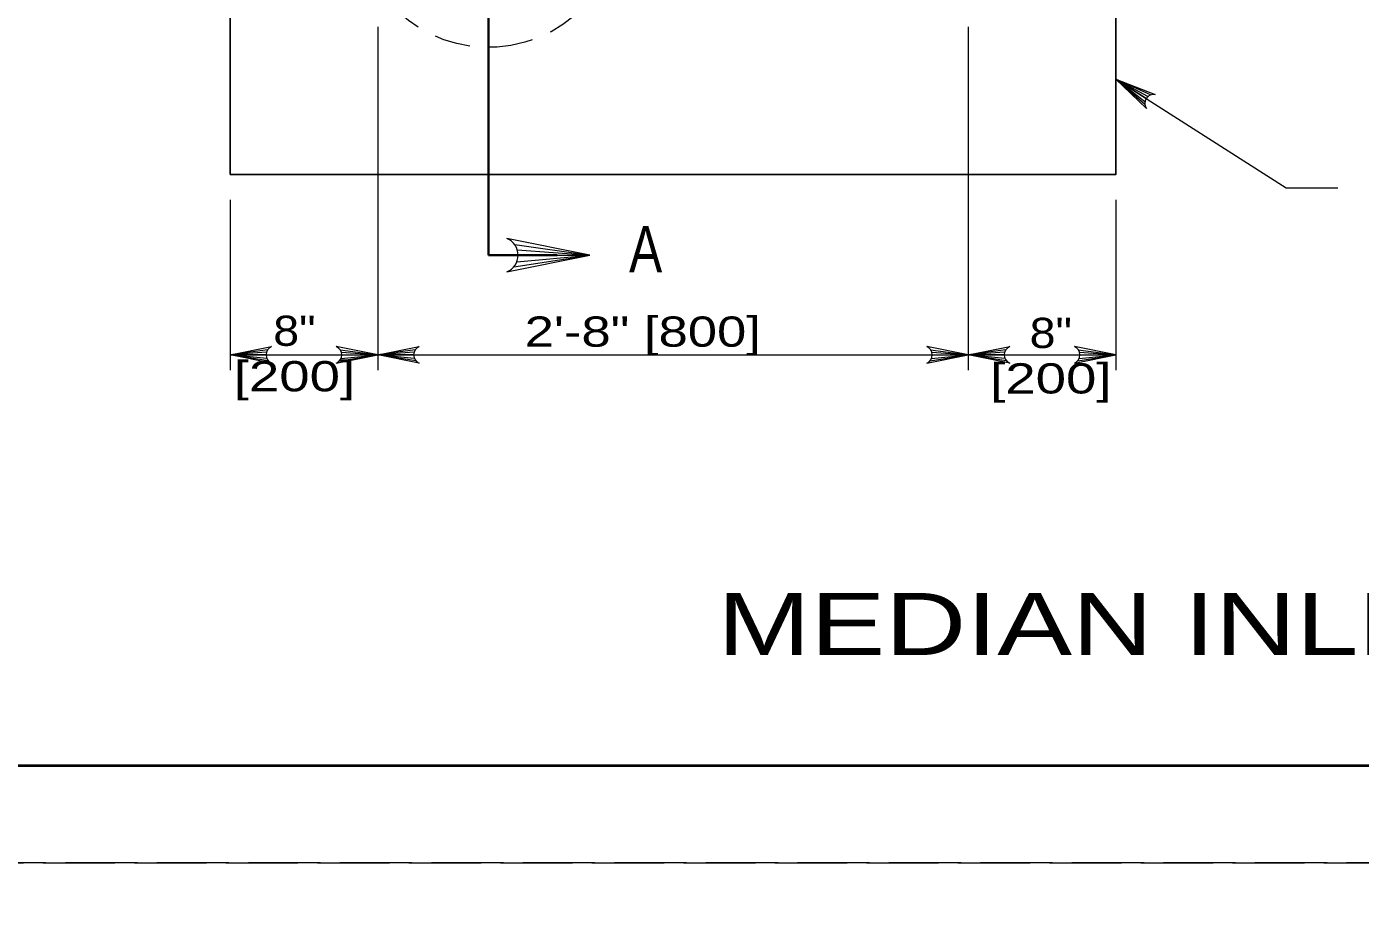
# Model space of a CAD drawing. Extents: x 339.1 to 373.1, y 1412.7 to 1456.7.
# Drawn here: x 344.17 to 351.05, y 1434.5 to 1439.06 of the extents above; entities that cross this region are included whole.
import ezdxf
from ezdxf.enums import TextEntityAlignment as Align

# ---------------------------------------------------------------- set-up
doc = ezdxf.new("R2010")
doc.units = 0
doc.header["$LTSCALE"] = 0.062
doc.linetypes.add('LONG_DASHED', pattern=[7.5, 6, -1.5])
doc.linetypes.add('MEDIUM_DASHED', pattern=[4.5, 3, -1.5])
doc.layers.add('1', color=7, linetype='Continuous', lineweight=13)

msp = doc.modelspace()

# ---------------------------------------------------------------- linework, layer by layer
at = {"layer": '1', "lineweight": 25}
msp.add_line((345.21833, 1441.19975), (345.21833, 1438.29742), dxfattribs=at)
at = {"layer": '1', "lineweight": 35}
for p, q in [((346.551, 1439.64317), (346.551, 1437.88075)), ((346.551, 1437.88075), (346.90592, 1437.88075))]:
    msp.add_line(p, q, dxfattribs=at)
at = {"layer": '1'}
for p, q in [((345.97983, 1439.05808), (345.97983, 1437.28725)), ((349.02583, 1439.05808), (349.02583, 1437.28725)), ((349.94333, 1438.689), (349.78733, 1438.789)), ((349.93683, 1438.6725), (349.78733, 1438.789)), ((349.93633, 1438.65792), (349.78733, 1438.789)), ((349.95242, 1438.6995), (349.78733, 1438.789)), ((349.96517, 1438.70725), (349.78733, 1438.789)), ((345.21833, 1438.16708), (345.21833, 1437.28725)), ((349.78733, 1438.16708), (349.78733, 1437.28725)), ((346.68667, 1437.935), (347.0745, 1437.88075)), ((346.68217, 1437.82083), (347.0745, 1437.88075)), ((346.697, 1437.84592), (347.0745, 1437.88075)), ((346.69983, 1437.90817), (347.0745, 1437.88075)), ((346.70383, 1437.88075), (347.0745, 1437.88075)), ((345.41225, 1437.39308), (345.21833, 1437.36592)), ((345.40567, 1437.37967), (345.21833, 1437.36592)), ((345.40367, 1437.36592), (345.21833, 1437.36592)), ((345.40708, 1437.3485), (345.21833, 1437.36592)), ((345.4145, 1437.33592), (345.21833, 1437.36592)), ((345.78367, 1437.33592), (345.97983, 1437.36592)), ((345.78592, 1437.39308), (345.97983, 1437.36592)), ((345.79108, 1437.3485), (345.97983, 1437.36592)), ((345.7925, 1437.37967), (345.97983, 1437.36592)), ((345.7945, 1437.36592), (345.97983, 1437.36592)), ((346.17375, 1437.39308), (345.97983, 1437.36592)), ((346.16717, 1437.37967), (345.97983, 1437.36592)), ((346.16517, 1437.36592), (345.97983, 1437.36592)), ((346.16858, 1437.3485), (345.97983, 1437.36592)), ((346.176, 1437.33592), (345.97983, 1437.36592)), ((348.82967, 1437.33592), (349.02583, 1437.36592)), ((348.83192, 1437.39308), (349.02583, 1437.36592)), ((348.83708, 1437.3485), (349.02583, 1437.36592)), ((348.8385, 1437.37967), (349.02583, 1437.36592)), ((348.8405, 1437.36592), (349.02583, 1437.36592)), ((349.21975, 1437.39308), (349.02583, 1437.36592)), ((349.21317, 1437.37967), (349.02583, 1437.36592)), ((349.21117, 1437.36592), (349.02583, 1437.36592)), ((349.21458, 1437.3485), (349.02583, 1437.36592)), ((349.222, 1437.33592), (349.02583, 1437.36592)), ((349.59117, 1437.33592), (349.78733, 1437.36592)), ((349.59342, 1437.39308), (349.78733, 1437.36592)), ((349.59858, 1437.3485), (349.78733, 1437.36592)), ((349.6, 1437.37967), (349.78733, 1437.36592)), ((349.602, 1437.36592), (349.78733, 1437.36592))]:
    msp.add_line(p, q, dxfattribs=at)
at = {"layer": '1', "linetype": 'LONG_DASHED'}
for points in [[(339.0605, 1434.7455), (373.0605, 1434.7455), (373.0605, 1456.7455), (339.0605, 1456.7455)], [(339.0605, 1412.7455), (373.0605, 1412.7455), (373.0605, 1434.7455), (339.0605, 1434.7455)]]:
    msp.add_lwpolyline(points, close=True, dxfattribs=at)
at = {"layer": '1', "lineweight": 25}
for points in [[(372.5605, 1435.2455), (341.0605, 1435.2455), (341.0605, 1456.2455)], [(349.78733, 1441.19975), (349.78733, 1438.29742), (345.21833, 1438.29742)]]:
    msp.add_lwpolyline(points, dxfattribs=at)
at = {"layer": '1', "lineweight": 40}
msp.add_lwpolyline([(341.0605, 1456.2455), (372.5605, 1456.2455), (372.5605, 1435.2455), (341.0605, 1435.2455)], close=True, dxfattribs=at)
at = {"layer": '1'}
for points in [[(349.9445, 1438.63742), (349.78733, 1438.789), (349.99075, 1438.7095)], [(349.78733, 1438.789), (350.66558, 1438.22808), (350.932, 1438.22808)], [(346.64617, 1437.79508), (347.0745, 1437.88075), (346.64617, 1437.96642)], [(345.4325, 1437.32308), (345.21833, 1437.36592), (345.4325, 1437.40875)], [(345.21833, 1437.36592), (345.69108, 1437.36592), (345.97983, 1437.36592), (348.12517, 1437.36592)], [(345.76567, 1437.32308), (345.97983, 1437.36592), (345.76567, 1437.40875)], [(346.194, 1437.32308), (345.97983, 1437.36592), (346.194, 1437.40875)], [(348.06875, 1437.36592), (349.02583, 1437.36592), (349.53117, 1437.36592), (349.78733, 1437.36592)], [(348.81167, 1437.32308), (349.02583, 1437.36592), (348.81167, 1437.40875)], [(349.24, 1437.32308), (349.02583, 1437.36592), (349.24, 1437.40875)], [(349.57317, 1437.32308), (349.78733, 1437.36592), (349.57317, 1437.40875)]]:
    msp.add_lwpolyline(points, dxfattribs=at)
for centre, radius, start, end in [((349.98224, 1438.66418), 0.04623, 79.4421, 215.26823), ((346.61156, 1437.88088), 0.09245, 292.08605, 67.91218), ((345.44981, 1437.36598), 0.04623, 112.08782, 247.91395), ((345.74838, 1437.36598), 0.04623, 292.08605, 67.91218), ((346.21131, 1437.36598), 0.04623, 112.08782, 247.91395), ((348.79435, 1437.36598), 0.04623, 292.08605, 67.91218), ((349.25728, 1437.36598), 0.04623, 112.08782, 247.91395), ((349.55584, 1437.36598), 0.04623, 292.08605, 67.91218)]:
    msp.add_arc(centre, radius, start, end, dxfattribs=at)
at = {"layer": '1', "linetype": 'MEDIUM_DASHED'}
msp.add_ellipse((346.55096, 1439.70825), major_axis=(0, 0.75581), ratio=0.944544, start_param=3.4075289, end_param=9.6907142, dxfattribs=at)

# ---------------------------------------------------------------- texts
at = {"layer": '1'}
for s, height, width, p in [('A', 0.24, 0.8, (347.276, 1437.79158)), ('2\'-8" [800]', 0.156, 1.3, (346.73775, 1437.4085)), ("MEDIAN INLETS (6' [1.8 m] to 20' [6.0 m])", 0.32, 1.35, (347.7315, 1435.81808))]:
    msp.add_text(s, height=height, dxfattribs=dict(at, width=width)).set_placement(p)
for s, width, p in [('8"', 1.15, (345.55012, 1437.41292)), ('8"', 1.15, (349.45179, 1437.40175)), ('[200]', 1.35, (345.55021, 1437.17833)), ('[200]', 1.35, (349.45187, 1437.16708))]:
    msp.add_text(s, height=0.156, dxfattribs=dict(at, width=width)).set_placement(p, align=Align.CENTER)

doc.saveas('drawing.dxf')
